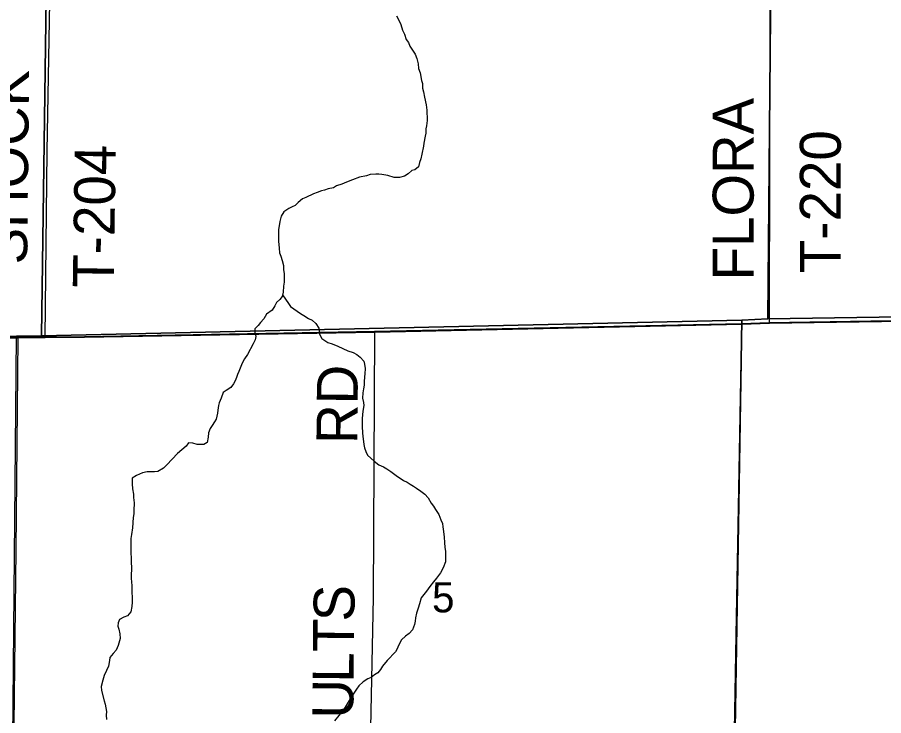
# Model space of a CAD drawing. Extents: x 36.7 to 70.7, y 0 to 22.
# Drawn here: x 42.275 to 43.478, y 19.304 to 20.274 of the extents above; entities that cross this region are included whole.
import ezdxf

# ---------------------------------------------------------------- set-up
doc = ezdxf.new("R2010")
doc.units = 0
for name, color, linetype in [('GM_X_County_Road', 7, 'Continuous'), ('GM_X_Minor_River', 7, 'Continuous'), ('GM_X_Section', 7, 'Continuous'), ('GM_X_Section_Text', 7, 'Continuous'), ('GM_X_Township_Road', 7, 'Continuous'), ('GM_X_Township_Road_Text', 7, 'Continuous')]:
    doc.layers.add(name, color=color, linetype=linetype)

msp = doc.modelspace()

# ---------------------------------------------------------------- linework, layer by layer
at = {"layer": 'GM_X_County_Road'}
for p, q in [((43.3192, 19.8488), (43.9954, 19.8602)), ((43.2808, 19.8475), (43.3192, 19.8488)), ((42.2764, 19.8288), (42.3139, 19.8289))]:
    msp.add_line(p, q, dxfattribs=at)
for points in [[(42.3139, 19.8289), (42.3687, 19.8294), (42.7715, 19.8367), (43.2808, 19.8475)], [(41.5658, 19.8236), (41.7763, 19.8238), (42.1317, 19.8276), (42.2346, 19.8287), (42.2764, 19.8288)]]:
    msp.add_lwpolyline(points, dxfattribs=at)
at = {"layer": 'GM_X_Minor_River'}
for points in [[(42.8014, 20.2758), (42.8044, 20.2708), (42.8077, 20.2636), (42.8099, 20.256), (42.8125, 20.2502), (42.815, 20.243), (42.8184, 20.2388), (42.8202, 20.2338), (42.8236, 20.2281), (42.8273, 20.2228), (42.8299, 20.2167), (42.8317, 20.209), (42.832, 20.2026), (42.8346, 20.1969), (42.8364, 20.1862), (42.8375, 20.182), (42.8378, 20.1752), (42.8389, 20.1702), (42.8407, 20.163), (42.8428, 20.1524), (42.8439, 20.1448), (42.8438, 20.1406), (42.8442, 20.1349), (42.8441, 20.1307), (42.8433, 20.1231), (42.8425, 20.119), (42.8424, 20.1129), (42.8416, 20.1087), (42.8396, 20.0989), (42.8391, 20.0947), (42.8367, 20.0837), (42.8352, 20.0773), (42.8336, 20.072), (42.832, 20.0663), (42.827, 20.0618), (42.8228, 20.0611), (42.8178, 20.0562), (42.8125, 20.0532), (42.806, 20.0514), (42.7984, 20.0515), (42.7898, 20.0542), (42.7814, 20.0555), (42.7773, 20.0559), (42.7731, 20.0559), (42.7651, 20.0553), (42.7598, 20.0538), (42.7503, 20.052), (42.7404, 20.0483), (42.7324, 20.045), (42.7259, 20.042), (42.7183, 20.0398), (42.7141, 20.0372), (42.7068, 20.0354), (42.7019, 20.0339), (42.6973, 20.0328), (42.6916, 20.0306), (42.6863, 20.0288), (42.676, 20.0236), (42.671, 20.0217), (42.6653, 20.0165), (42.6611, 20.0123), (42.6569, 20.0105), (42.6523, 20.0083), (42.6454, 20.0038), (42.6415, 19.9974), (42.6399, 19.9902), (42.6379, 19.9788), (42.6377, 19.9629), (42.6388, 19.953), (42.6394, 19.9469), (42.6413, 19.9419), (42.6431, 19.9359), (42.6446, 19.929), (42.6449, 19.9237), (42.6459, 19.9176), (42.6458, 19.9058), (42.645, 19.9005), (42.6445, 19.8922), (42.6429, 19.8861), (42.6398, 19.882), (42.6352, 19.8775), (42.6329, 19.8733), (42.6291, 19.8673), (42.6214, 19.8617), (42.6175, 19.8549), (42.6129, 19.85), (42.6098, 19.8459), (42.6052, 19.841), (42.6052, 19.8364), (42.6063, 19.8307), (42.6054, 19.8258), (42.6027, 19.8201), (42.595, 19.8054), (42.5907, 19.7994), (42.5876, 19.7933), (42.5829, 19.782), (42.581, 19.7778), (42.5794, 19.7737), (42.5779, 19.7691), (42.5755, 19.7646)], [(42.6435, 19.8883), (42.6519, 19.8765), (42.6545, 19.872), (42.6685, 19.8623), (42.673, 19.8596), (42.6794, 19.8557), (42.6847, 19.853), (42.6895, 19.8484), (42.694, 19.8423), (42.6947, 19.8339), (42.698, 19.8278), (42.7063, 19.822), (42.7124, 19.8201), (42.7203, 19.817), (42.7271, 19.8139), (42.7342, 19.8107), (42.7414, 19.8084), (42.7467, 19.8057), (42.7512, 19.8018), (42.7561, 19.7961), (42.7572, 19.7919), (42.7579, 19.7862), (42.7578, 19.7786), (42.7574, 19.7744), (42.7569, 19.7676), (42.7568, 19.7627), (42.756, 19.7577), (42.7548, 19.7521), (42.7544, 19.7449), (42.7558, 19.7388), (42.7561, 19.7346), (42.7553, 19.7297), (42.7545, 19.7225), (42.754, 19.7156), (42.7539, 19.7054), (42.7542, 19.6966), (42.7549, 19.6917), (42.756, 19.6849), (42.7563, 19.6803), (42.757, 19.6761), (42.7592, 19.6708), (42.7614, 19.6658), (42.7704, 19.6574), (42.7772, 19.6524), (42.7836, 19.6496), (42.7881, 19.6466), (42.7938, 19.6431), (42.8013, 19.6377), (42.8115, 19.6307), (42.8164, 19.628), (42.8205, 19.6253), (42.8254, 19.6226), (42.8296, 19.6199), (42.8356, 19.6157), (42.8408, 19.6114), (42.8457, 19.6065), (42.8498, 19.5992), (42.8528, 19.595), (42.8558, 19.5904), (42.8606, 19.5831), (42.8632, 19.5759), (42.8654, 19.5706), (42.8657, 19.5664), (42.8668, 19.5595), (42.8679, 19.5519), (42.8681, 19.5443), (42.8688, 19.5375), (42.8695, 19.5322), (42.8698, 19.5257), (42.8694, 19.5178), (42.8666, 19.5091), (42.8627, 19.5023), (42.857, 19.4951), (42.8531, 19.4898), (42.8481, 19.4831), (42.8431, 19.4767), (42.8396, 19.4721), (42.8358, 19.4676), (42.8334, 19.4593), (42.8318, 19.4532), (42.8295, 19.4461), (42.8279, 19.44), (42.8275, 19.4351), (42.8266, 19.4305), (42.8239, 19.4233), (42.8193, 19.4181), (42.8143, 19.4143), (42.8086, 19.4091), (42.8043, 19.4012), (42.8024, 19.3966), (42.8, 19.3925), (42.7885, 19.3805), (42.7824, 19.3725), (42.7796, 19.368), (42.7758, 19.3635), (42.7712, 19.3605), (42.7666, 19.3568), (42.7617, 19.3549), (42.7552, 19.3508), (42.7494, 19.3452), (42.746, 19.3407)], [(42.5755, 19.7646), (42.5717, 19.7597), (42.5652, 19.7556), (42.561, 19.7526), (42.5582, 19.7451), (42.5555, 19.7386), (42.5547, 19.7345), (42.5535, 19.7284), (42.5531, 19.7239), (42.5515, 19.7159), (42.5491, 19.7118), (42.546, 19.7069), (42.543, 19.7027), (42.5406, 19.6967), (42.5402, 19.6906), (42.539, 19.6834), (42.534, 19.6804), (42.5249, 19.6805), (42.5188, 19.6825), (42.5131, 19.6829), (42.5097, 19.6784), (42.5039, 19.6731), (42.4978, 19.6679), (42.4901, 19.66), (42.4828, 19.6521), (42.4782, 19.6476), (42.4702, 19.6431), (42.4657, 19.6428), (42.4603, 19.6425), (42.4554, 19.6425), (42.4493, 19.6411), (42.4409, 19.6374), (42.4348, 19.6337), (42.4347, 19.6261), (42.4354, 19.6188), (42.4365, 19.6116), (42.4368, 19.6067), (42.4375, 19.5995), (42.437, 19.5888), (42.4369, 19.5843), (42.4361, 19.579), (42.4352, 19.5646), (42.4339, 19.5555), (42.4331, 19.5498), (42.433, 19.5433), (42.4329, 19.5297), (42.4332, 19.5232), (42.4335, 19.5152), (42.4338, 19.511), (42.4337, 19.5061), (42.4333, 19.5008), (42.4332, 19.4947), (42.4339, 19.4894), (42.4343, 19.4845), (42.4342, 19.4803), (42.4345, 19.4761), (42.4348, 19.4674), (42.4348, 19.4617), (42.4343, 19.4556), (42.4327, 19.448), (42.4281, 19.4424), (42.4231, 19.4409), (42.417, 19.4376), (42.4151, 19.4327), (42.415, 19.4281), (42.4161, 19.4239), (42.4176, 19.4178), (42.4179, 19.411), (42.4151, 19.4015), (42.4124, 19.3947), (42.4085, 19.3902), (42.4039, 19.3846), (42.4035, 19.3804), (42.4019, 19.3725), (42.3992, 19.3668), (42.3957, 19.3596), (42.3941, 19.3532), (42.3917, 19.3445), (42.3924, 19.3388), (42.396, 19.3247), (42.3971, 19.3197), (42.3989, 19.3099), (42.3988, 19.3045), (42.3991, 19.2985)], [(42.746, 19.3407), (42.7425, 19.3354), (42.739, 19.3305), (42.7359, 19.3248), (42.729, 19.3135), (42.7247, 19.3083), (42.7216, 19.3041), (42.7155, 19.297)]]:
    msp.add_lwpolyline(points, dxfattribs=at)
at = {"layer": 'GM_X_Section'}
for points in [[(44.3293, 20.877), (44.3136, 19.8697), (44.2753, 19.8692), (43.3171, 19.855), (43.3259, 20.8559)], [(43.3259, 20.8559), (43.3171, 19.855), (43.2807, 19.8534), (42.3088, 19.8313), (42.3229, 20.8368)], [(42.3229, 20.8368), (42.3088, 19.8313), (42.2743, 19.8312), (41.3623, 19.8182), (41.3719, 20.8169)], [(44.2753, 19.8692), (44.2682, 18.9088), (43.2658, 18.9165), (43.2807, 19.8534), (43.3171, 19.855)], [(43.2807, 19.8534), (43.2658, 18.9165), (42.2659, 18.914), (42.2743, 19.8312), (42.3088, 19.8313)]]:
    msp.add_lwpolyline(points, close=True, dxfattribs=at)
at = {"layer": 'GM_X_Township_Road'}
for p, q in [((43.3192, 19.8488), (43.3216, 20.8505)), ((43.2731, 19.4156), (43.2808, 19.8475)), ((43.2808, 19.8475), (43.3192, 19.8488)), ((42.2764, 19.8288), (42.3139, 19.8289))]:
    msp.add_line(p, q, dxfattribs=at)
for points in [[(45.5934, 20.8969), (41.3748, 20.8969), (41.3661, 20.3009), (41.3664, 20.1648), (41.3664, 20.1643), (41.3664, 20.1389), (41.3665, 20.1284), (41.3659, 20.06), (41.3629, 19.8535), (41.3628, 19.8405), (41.3626, 19.8228), (41.3623, 19.8162), (41.3671, 19.8162), (41.5405, 19.8156), (41.5474, 19.8155), (41.5546, 19.8154), (41.5623, 19.8154), (42.2762, 19.8294), (42.3137, 19.8294), (42.3685, 19.83), (42.7713, 19.8373), (43.2806, 19.8481), (43.3189, 19.8494), (44.0245, 19.8612)], [(42.3139, 19.8289), (42.3169, 20.0878), (42.3206, 20.2949), (42.3235, 20.5136), (42.3259, 20.7139), (42.3271, 20.8313), (42.3273, 20.8969)], [(44.0245, 19.8612), (43.3189, 19.8494), (43.2806, 19.8481), (42.7713, 19.8373), (42.3685, 19.83), (42.3137, 19.8294), (42.2762, 19.8294), (41.5623, 19.8154), (41.5546, 19.8154), (41.5474, 19.8155), (41.5405, 19.8156), (41.3671, 19.8162), (41.3623, 19.8162), (41.3441, 19.4051), (41.344, 19.4017), (41.3037, 18.4227), (41.3025, 18.3936), (41.3022, 18.3874), (41.2661, 17.5372), (41.2499, 16.8815)], [(42.2689, 19.0716), (42.2698, 19.1678), (42.2709, 19.2917), (42.2739, 19.534), (42.2764, 19.8288)], [(42.7688, 19.4225), (42.7697, 19.468), (42.7715, 19.8367)], [(42.76, 18.8877), (42.7602, 18.8965), (42.7612, 18.9559), (42.765, 19.2416), (42.7688, 19.4225)], [(43.2619, 18.7104), (43.262, 18.7192), (43.2645, 18.9386), (43.2731, 19.4156)]]:
    msp.add_lwpolyline(points, dxfattribs=at)

# ---------------------------------------------------------------- texts
at = {"layer": 'GM_X_Section_Text'}
msp.add_text('5', height=0.0419, rotation=0, dxfattribs=at).set_placement((42.8509, 19.4474))
at = {"layer": 'GM_X_Township_Road_Text'}
for s, height, rotation, p in [('SHOCK', 0.05682, 89.39, (42.2889, 19.9304)), ('FLORA', 0.05682, 90, (43.2973, 19.9085)), ('T-220', 0.05682, 90, (43.4183, 19.9185)), ('T-204', 0.05682, 89.1569, (42.4091, 19.8979)), ('RD', 0.05682, 89.5063, (42.7473, 19.6812)), ('S', 0.0568, 88.6124, (42.7428, 19.4343)), ('T', 0.0568, 89.4, (42.7423, 19.392)), ('L', 0.0568, 89.4257, (42.7419, 19.3496)), ('U', 0.0568, 89.4244, (42.7414, 19.2996))]:
    msp.add_text(s, height=height, rotation=rotation, dxfattribs=at).set_placement(p)

doc.saveas('drawing.dxf')
